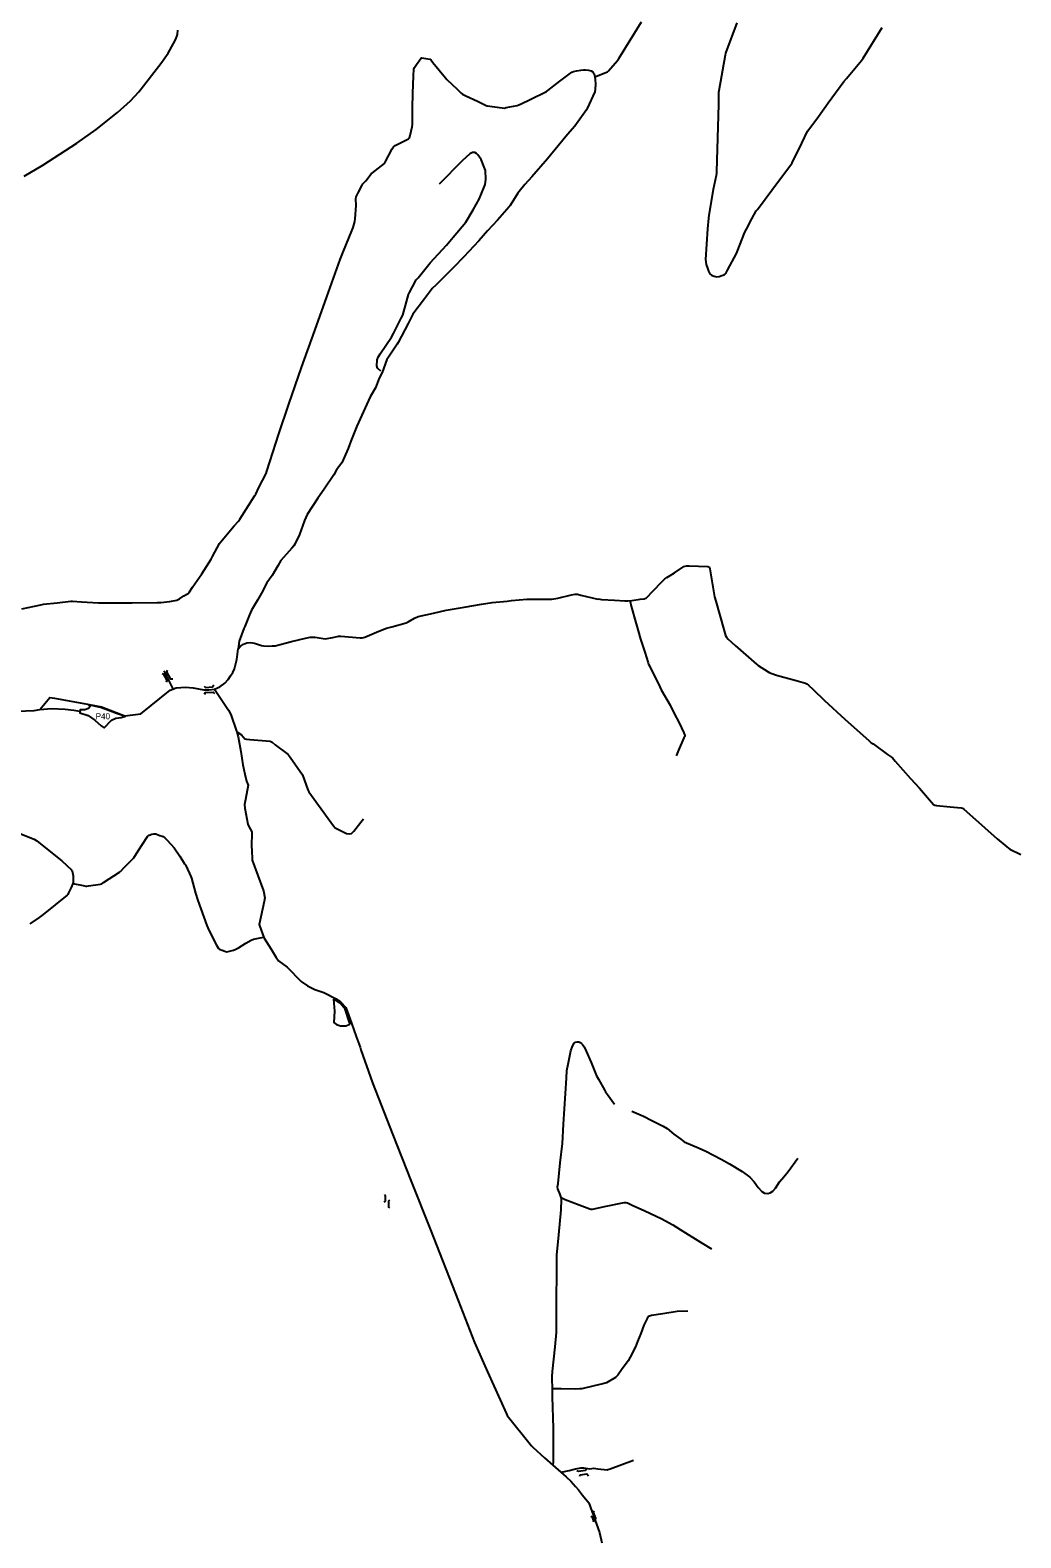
# Model space of a CAD drawing. Extents: x -439169 to -431590, y -1130011 to -1121081.
# Drawn here: x -436040 to -434407, y -1125656 to -1123172 of the extents above; entities that cross this region are included whole.
import ezdxf

# ---------------------------------------------------------------- set-up
doc = ezdxf.new("R2010")
doc.units = 0
for name, color, linetype in [('11811012_místní  komunikace_Stav', 7, 'Continuous'), ('11900012_účelová komunikace_Stav', 7, 'Continuous'), ('11930011_silniční most _ estakáda_Stav', 7, 'Continuous'), ('12080013_parkoviště mimo prostor komunikace_Stav', 7, 'Continuous')]:
    doc.layers.add(name, color=color, linetype=linetype)

msp = doc.modelspace()

# ---------------------------------------------------------------- linework, layer by layer
at = {"layer": '11811012_místní  komunikace_Stav'}
for points in [[(-436049.6, -1123412.6), (-436018.7, -1123394.7), (-435962.8, -1123358.3), (-435930.5, -1123335.7), (-435895.5, -1123307.6), (-435874.4, -1123288.7), (-435860.3, -1123273.9), (-435824.1, -1123227.2), (-435812.2, -1123209.9), (-435803.3, -1123194.1), (-435799.4, -1123186.7), (-435796.9, -1123179.4), (-435796.2, -1123172.1)], [(-435669.9, -1124181.7), (-435668.3, -1124182.3), (-435658.6, -1124185.6), (-435654.8, -1124186.5), (-435646, -1124186.8), (-435640.9, -1124186.6), (-435635.8, -1124186.2), (-435609.1, -1124179.2), (-435586.1, -1124173.7), (-435577.9, -1124172.1), (-435574.9, -1124172.1), (-435569.8, -1124172.3), (-435556.8, -1124174.4), (-435553.7, -1124174.6), (-435540.9, -1124172.5), (-435531.3, -1124170.5), (-435527.7, -1124170.4), (-435495.7, -1124173), (-435492.5, -1124173), (-435488.1, -1124171.9), (-435464.8, -1124162.2), (-435452.3, -1124157.2), (-435443.7, -1124155.2), (-435420.2, -1124148.4), (-435416.6, -1124146.8), (-435406.5, -1124140.8), (-435400.1, -1124137.8), (-435374.8, -1124132.3), (-435353.9, -1124127.6), (-435324.6, -1124122.6), (-435295.9, -1124117.7), (-435278.2, -1124115.2), (-435253.8, -1124112.9), (-435246.3, -1124111.9), (-435221, -1124109.4), (-435202.3, -1124109.5), (-435180.1, -1124109.4), (-435176.8, -1124109.1), (-435170, -1124107.6), (-435147.8, -1124102.5), (-435141.4, -1124101.2), (-435137.9, -1124101.4), (-435132, -1124103.1), (-435103.9, -1124109.5)], [(-435699.2, -1124208.8), (-435696.7, -1124191.4), (-435693.2, -1124186.8), (-435687.8, -1124183.6), (-435682.3, -1124181.2), (-435676.2, -1124180.9), (-435670, -1124181.8)], [(-436074, -1124294.5), (-436033, -1124292.8), (-436023.7, -1124291.1), (-436007.1, -1124271.2), (-435999.6, -1124272.3), (-435944.8, -1124282.4), (-435921.9, -1124287), (-435883.8, -1124301.4), (-435857.3, -1124298.1), (-435808.9, -1124259.2), (-435799.1, -1124255.4), (-435783.7, -1124254.6), (-435770.8, -1124255.4), (-435753.3, -1124259), (-435745.1, -1124259), (-435735.9, -1124257.5), (-435727.2, -1124253.9), (-435718.6, -1124247.6), (-435713.1, -1124241.7), (-435709.2, -1124235.8), (-435705.7, -1124230), (-435703.1, -1124224.3), (-435701.3, -1124217.7), (-435699.2, -1124208.8)], [(-435735.9, -1124257.5), (-435712.5, -1124292.4), (-435708.7, -1124299.6), (-435699.8, -1124326.7), (-435699.2, -1124328.2), (-435696.6, -1124336.1), (-435692.5, -1124360.5), (-435688.9, -1124382.2), (-435685.8, -1124397.5), (-435683, -1124409.4), (-435680.5, -1124415.7), (-435684.6, -1124439.6), (-435686.1, -1124447.6), (-435685.7, -1124453.7), (-435680.8, -1124480.1), (-435679.9, -1124482.7), (-435674.5, -1124492.6), (-435674.7, -1124517.9), (-435674.1, -1124522), (-435673.6, -1124539.5), (-435654.8, -1124589.9), (-435652.7, -1124601.3), (-435653.7, -1124607.6), (-435662.2, -1124645.6), (-435655.9, -1124662.6), (-435653.7, -1124667.9), (-435642.6, -1124686.2), (-435634.4, -1124699.6), (-435630.3, -1124705), (-435615.9, -1124715.8), (-435593, -1124739.2), (-435582.3, -1124746.6), (-435570.5, -1124752.3), (-435555.4, -1124757.5), (-435535.4, -1124767.8), (-435528, -1124772.6), (-435519.5, -1124782), (-435510.2, -1124807.8)], [(-436023.7, -1124291.1), (-436004.5, -1124289.5), (-435981.7, -1124290.7), (-435967.5, -1124292.2), (-435957.6, -1124294.1)]]:
    msp.add_lwpolyline(points, dxfattribs=at)
for points in [[(-435942.7, -1124283.3), (-435940.8, -1124286.3), (-435943.6, -1124289.8), (-435949.5, -1124291.7), (-435957.3, -1124291.6), (-435957.9, -1124296.6), (-435944.1, -1124301.3), (-435932.9, -1124309), (-435922.3, -1124318.1), (-435917.6, -1124321.6), (-435905.6, -1124308.7), (-435898.4, -1124305.3), (-435889.6, -1124304.2), (-435882.2, -1124302.4), (-435885.7, -1124301.7), (-435897.4, -1124297.8), (-435916.1, -1124290.8), (-435923.6, -1124287.9), (-435931.1, -1124286.1)], [(-435539.8, -1124768.2), (-435538.1, -1124788.1), (-435539.3, -1124807), (-435534.7, -1124810.1), (-435528.3, -1124812.1), (-435519.6, -1124812.1), (-435514.1, -1124810.1), (-435512.6, -1124808.6), (-435520.5, -1124784.7), (-435528.7, -1124775), (-435536.5, -1124770)]]:
    msp.add_lwpolyline(points, close=True, dxfattribs=at)
at = {"layer": '11900012_účelová komunikace_Stav'}
msp.add_line((-435803.7, -1124257.2), (-435818.6, -1124227.4), dxfattribs=at)
for points in [[(-435109.1, -1123249.1), (-435088.3, -1123240.8), (-435086.5, -1123239.1), (-435071.5, -1123221.8), (-435069.3, -1123218.8), (-435032, -1123158.1)], [(-434874.9, -1123159.9), (-434893.7, -1123210.1), (-434894.2, -1123213), (-434904.5, -1123272.1), (-434905.1, -1123275), (-434905.4, -1123294.6), (-434908.6, -1123405.1), (-434908.6, -1123407.6), (-434909.3, -1123411.3), (-434914.1, -1123434.6), (-434921.5, -1123476.7), (-434922, -1123481.7), (-434923.7, -1123499.2), (-434926.6, -1123549.8), (-434925.5, -1123557.9), (-434923.5, -1123564.2), (-434922, -1123569.3), (-434919.8, -1123573.4), (-434916.8, -1123575.8), (-434912.6, -1123577.3), (-434908, -1123578.4), (-434904.1, -1123577.8), (-434899.9, -1123576.4), (-434896.2, -1123575.1), (-434893.3, -1123572.7), (-434890.5, -1123567.3), (-434875.6, -1123540), (-434874.3, -1123537.1), (-434862.1, -1123505), (-434859.4, -1123499.9), (-434850.2, -1123482.9), (-434843.2, -1123469.5), (-434841.3, -1123467.3), (-434805, -1123418.6), (-434786.3, -1123393.8), (-434784.1, -1123390.7), (-434768.2, -1123358.2), (-434758.5, -1123338.5), (-434756.4, -1123335.9), (-434740.8, -1123314.5), (-434724.4, -1123291.8), (-434698.6, -1123256.8), (-434694.2, -1123251.6), (-434669.5, -1123222.1), (-434667.1, -1123218.3), (-434635.5, -1123167.8)], [(-435650.9, -1123902.2), (-435649.8, -1123898.5), (-435629.6, -1123837), (-435613.2, -1123788.3), (-435592.3, -1123728), (-435570.6, -1123666.7), (-435550.5, -1123611.2), (-435528.5, -1123550), (-435524.3, -1123539.1), (-435508.4, -1123500.1), (-435507.5, -1123497.2), (-435504.7, -1123487.1), (-435503.8, -1123482.7), (-435502.4, -1123461), (-435503.1, -1123449.9), (-435502.4, -1123446.5), (-435500.9, -1123443.2), (-435498.6, -1123438.9), (-435492.6, -1123427.3), (-435491.3, -1123425.3), (-435486.6, -1123420), (-435477.4, -1123408.8), (-435475.6, -1123407.1), (-435455.8, -1123391.5), (-435454.5, -1123389.4), (-435442.9, -1123367.6), (-435440.8, -1123364.2), (-435438.3, -1123362), (-435416.3, -1123351.3), (-435414.5, -1123349.7), (-435413.6, -1123345.5), (-435410, -1123331.4), (-435409.8, -1123327.6), (-435409.7, -1123300), (-435409.2, -1123276.6), (-435407.7, -1123247.2), (-435407.1, -1123236.3), (-435406.1, -1123233.6), (-435403.1, -1123228.7), (-435396, -1123218.7), (-435394.3, -1123217.4), (-435391.1, -1123218), (-435381.1, -1123220), (-435378.7, -1123221.3), (-435375.9, -1123225.3), (-435355.4, -1123250.8), (-435352.8, -1123253.4), (-435336, -1123269.5), (-435329.2, -1123275.9), (-435327, -1123277.5), (-435321.8, -1123280.4), (-435302.6, -1123289.1), (-435288.3, -1123296), (-435286.5, -1123296.7), (-435281.9, -1123297.3), (-435257.8, -1123300.4), (-435255.4, -1123299.7), (-435237.3, -1123295.9), (-435234.4, -1123295.2), (-435230.3, -1123293.3), (-435215.7, -1123286.3), (-435188.7, -1123273.1), (-435186.5, -1123271.4), (-435166.6, -1123256.2), (-435146.8, -1123241.5), (-435144.4, -1123240.4), (-435139.3, -1123239.2), (-435131.9, -1123237.8), (-435127.8, -1123237.3), (-435124.5, -1123237.3), (-435119.8, -1123237.8), (-435115.3, -1123239.3), (-435112.6, -1123240.5), (-435110.4, -1123244.2), (-435109.1, -1123249.1), (-435108.3, -1123253.8), (-435108.2, -1123260.2), (-435108.3, -1123269.9), (-435109.3, -1123273.7), (-435121.5, -1123300.9), (-435122.8, -1123303.3), (-435142.3, -1123330), (-435154, -1123343.8), (-435169.5, -1123362.5), (-435187.1, -1123383.9), (-435213.1, -1123413.5), (-435224.2, -1123426.5), (-435233.9, -1123437.6), (-435236, -1123440.8), (-435248.5, -1123460.9), (-435250.4, -1123463), (-435269.7, -1123484.8), (-435285.8, -1123502.6), (-435300.2, -1123518.9), (-435324.7, -1123545.3), (-435341.7, -1123563.3), (-435370.5, -1123591.4), (-435377.1, -1123597.9), (-435378.3, -1123599.2), (-435389.7, -1123614.7), (-435409, -1123640.1)], [(-435461.6, -1123734.1), (-435467, -1123728.7), (-435468.1, -1123725), (-435467.5, -1123715.1), (-435466.2, -1123710.6), (-435462.9, -1123705.1), (-435443.9, -1123678), (-435440.8, -1123671.7), (-435428.1, -1123646.4), (-435425.7, -1123641.6), (-435419.6, -1123619.6), (-435415.9, -1123607.7), (-435414.5, -1123604), (-435409.3, -1123594.9), (-435403.3, -1123583.6), (-435400, -1123580.1), (-435380.2, -1123555.4), (-435353.7, -1123526.5), (-435342.3, -1123513), (-435321.7, -1123488.4), (-435309.7, -1123467.9), (-435299.6, -1123450.4), (-435296.8, -1123444.1), (-435289.8, -1123426.3), (-435289.1, -1123422.4), (-435288.5, -1123417.6), (-435289.3, -1123403.1), (-435291.5, -1123398), (-435296.5, -1123385.3), (-435301.8, -1123377.7), (-435304.2, -1123375.1), (-435306.8, -1123373.6), (-435310.5, -1123373.8), (-435315.2, -1123375.8), (-435327.6, -1123387.1), (-435365.6, -1123425.9)], [(-435409, -1123640.1), (-435410.3, -1123642.2), (-435416.9, -1123655.3), (-435433.1, -1123686.7), (-435434.8, -1123689.1), (-435450.3, -1123712.2), (-435451.7, -1123714.4), (-435459.6, -1123736.3), (-435464.4, -1123745.3), (-435470.7, -1123761.3), (-435479.4, -1123775.9), (-435501.3, -1123824.3), (-435511.4, -1123849.4), (-435515.4, -1123861.1), (-435526.1, -1123885.1), (-435534.6, -1123896.3), (-435539.4, -1123904.5), (-435555.3, -1123928.5), (-435565.3, -1123943), (-435583.2, -1123970.1), (-435587.4, -1123980.1), (-435595.8, -1124002.8), (-435603.4, -1124019), (-435605, -1124021.7), (-435608.3, -1124025.4), (-435626.5, -1124045.9), (-435631.6, -1124054.6), (-435641, -1124070.2), (-435649.6, -1124082.5), (-435658.2, -1124099.7), (-435665, -1124110.9), (-435674.9, -1124127.5), (-435677.9, -1124135.2), (-435685.7, -1124154.6), (-435687.3, -1124157.8), (-435695.4, -1124178.9), (-435696.7, -1124191.4)], [(-436053.2, -1124125.4), (-436021.8, -1124118.7), (-436017.8, -1124117.9), (-435995.2, -1124115.3), (-435972.6, -1124112.7), (-435969.8, -1124112.9), (-435954.7, -1124113.7), (-435926.9, -1124115.7), (-435914.2, -1124115.6), (-435871.6, -1124115.5), (-435830.3, -1124115.1), (-435824.2, -1124114.7), (-435809.9, -1124113.1), (-435800.5, -1124111.9), (-435797.8, -1124111.2), (-435793.7, -1124109.1), (-435786.1, -1124103.9), (-435779.4, -1124099.9), (-435777.1, -1124097.6), (-435771.8, -1124089.8), (-435756.6, -1124067.6), (-435741.4, -1124043.5), (-435739.2, -1124039.1), (-435727.6, -1124017.6), (-435725.8, -1124015.5), (-435703.2, -1123988.9), (-435696.5, -1123980.9), (-435694.2, -1123977.6), (-435669.2, -1123938.8), (-435667.6, -1123936.3), (-435662.6, -1123925.5), (-435650.9, -1123902.2)], [(-434990.3, -1124073.6), (-434985, -1124070.4), (-434977.8, -1124065.8), (-434962.3, -1124055.8), (-434958.3, -1124054.3), (-434953.8, -1124054.3), (-434923.1, -1124055.8), (-434920.4, -1124056.7), (-434919.6, -1124059.4), (-434918.2, -1124069.2), (-434911.7, -1124105.6), (-434909.6, -1124112.7), (-434896.4, -1124159.2), (-434893.6, -1124169.2), (-434892.3, -1124172), (-434889.2, -1124175.2), (-434877.6, -1124185.6), (-434842.5, -1124216.7), (-434839.7, -1124218.9), (-434823.4, -1124229.3), (-434820.8, -1124230.7), (-434817.2, -1124231.9), (-434809.5, -1124234.9), (-434777.5, -1124243.6), (-434762.1, -1124248), (-434760, -1124249), (-434757, -1124251.2), (-434749.4, -1124258.3), (-434730.4, -1124276.5), (-434697.4, -1124307.1), (-434657.2, -1124342.7), (-434653.6, -1124345.9), (-434650.6, -1124348), (-434627.1, -1124365.3), (-434618.6, -1124371.1), (-434616.6, -1124373.5), (-434614.1, -1124376.1), (-434588.9, -1124404.7), (-434574.1, -1124421), (-434550.9, -1124447.6), (-434548.8, -1124449), (-434546.2, -1124449.3), (-434523.8, -1124451.4), (-434505.5, -1124453.4), (-434503.2, -1124453.8), (-434501, -1124455.5), (-434486.7, -1124468.3), (-434445.9, -1124504.1), (-434430.2, -1124517.5), (-434427.6, -1124519.7), (-434425, -1124521.1), (-434407.1, -1124529.9)], [(-435103.6, -1124109.1), (-435098.1, -1124110.1), (-435076.5, -1124111.2), (-435059.9, -1124112), (-435054.7, -1124112.4), (-435047.9, -1124111.7), (-435034.5, -1124109.5), (-435027.6, -1124109), (-435025.3, -1124108), (-435024.7, -1124107.6), (-434999.9, -1124082.2), (-434993.5, -1124076), (-434990.3, -1124073.6)], [(-435050.8, -1124113.5), (-435049.1, -1124120.8), (-435042.2, -1124146), (-435037.5, -1124161.8), (-435034.1, -1124175.2), (-435026.9, -1124197), (-435021.3, -1124214.5), (-435020.5, -1124216.3), (-435019.1, -1124219.5), (-435002, -1124254.1), (-434999.6, -1124259), (-434985.2, -1124284.2), (-434978.1, -1124297.6), (-434969.9, -1124313.4), (-434962.7, -1124329.5), (-434961, -1124334), (-434960.8, -1124335.7), (-434962.2, -1124337.9), (-434971.5, -1124358.2), (-434974.5, -1124366.5), (-434974.9, -1124367.6)], [(-435699.2, -1124328.2), (-435691.1, -1124333.2), (-435685.7, -1124339.5), (-435683, -1124340.2), (-435677.8, -1124340.6), (-435644.2, -1124343.5), (-435640.6, -1124344.8), (-435635.6, -1124349.2), (-435614.2, -1124365.6), (-435611.3, -1124369.7), (-435590.6, -1124399), (-435582, -1124423.8), (-435580.3, -1124426.8), (-435560.3, -1124454.6), (-435548.3, -1124471), (-435539.8, -1124482.6), (-435537.1, -1124485.9), (-435530.2, -1124489.6), (-435518.3, -1124495.3), (-435513.8, -1124496), (-435509.8, -1124495.5), (-435506.2, -1124491.8), (-435494.5, -1124477), (-435490.1, -1124471.1)], [(-436064.6, -1124492.1), (-436033.1, -1124505), (-436028.3, -1124507.6), (-436022.6, -1124512.5), (-435987.6, -1124540.4), (-435971.6, -1124555.5), (-435970.2, -1124557.1), (-435968.9, -1124565.2), (-435968.7, -1124572.4), (-435968.7, -1124576.1), (-435969.4, -1124577.9), (-435972.2, -1124584.2), (-435976.2, -1124593.2), (-435977.3, -1124595.8), (-435978.6, -1124596.9), (-436018.2, -1124629.1), (-436024.5, -1124633.7), (-436038.3, -1124643.3), (-436040.1, -1124644.9)], [(-435969.4, -1124577.9), (-435952, -1124581.3), (-435947.9, -1124582), (-435946.2, -1124582), (-435943.4, -1124581.8), (-435923.9, -1124579), (-435921.3, -1124578.2), (-435918.7, -1124576.3), (-435892.5, -1124559.4), (-435890.5, -1124557.9), (-435885, -1124552.1), (-435870.8, -1124537.6), (-435868.9, -1124535.5), (-435861.7, -1124523.9), (-435846.2, -1124500.2), (-435843.7, -1124498.2), (-435838.9, -1124496.5), (-435835.9, -1124495.9), (-435832.6, -1124496.2), (-435827.3, -1124498), (-435820.5, -1124500.4), (-435817.7, -1124502.6), (-435813.7, -1124506.6), (-435802.5, -1124519.2), (-435793.1, -1124533.1), (-435785, -1124545.3), (-435783.4, -1124547.2), (-435776.9, -1124561.6), (-435774.6, -1124566.1), (-435773.7, -1124569.2), (-435767.1, -1124593.6), (-435763, -1124605.8), (-435748.4, -1124647.1), (-435746.8, -1124651), (-435739.4, -1124666), (-435732.6, -1124679.3), (-435729, -1124684.8), (-435727, -1124686.6), (-435723.4, -1124687.6), (-435718.8, -1124689.5), (-435716.1, -1124690.2), (-435713.5, -1124690.1), (-435704.6, -1124687.5), (-435700.5, -1124685.9), (-435696.1, -1124683.8), (-435684.1, -1124676.4), (-435675.2, -1124671.2), (-435671.3, -1124669.6), (-435660.4, -1124667.3), (-435654.7, -1124666.1)], [(-435510.2, -1124807.8), (-435502.1, -1124829.7), (-435495.8, -1124847.4), (-435494.5, -1124851.7), (-435475.4, -1124906.5), (-435442.1, -1124991.9), (-435412.4, -1125067.1), (-435380, -1125148.4), (-435334.5, -1125265), (-435307.5, -1125333.8), (-435285.9, -1125382.5), (-435254.8, -1125451.7), (-435253.5, -1125454.5), (-435213.4, -1125504.3), (-435211.5, -1125506.3), (-435192.1, -1125523.9), (-435178.3, -1125536.1), (-435156.1, -1125555.3), (-435148.7, -1125562.6), (-435140.8, -1125571.5), (-435136.2, -1125576.7), (-435129.2, -1125585.5), (-435119, -1125598.3), (-435101.6, -1125646.9), (-435097.4, -1125664)], [(-435178.3, -1125536.1), (-435177.2, -1125532), (-435177.2, -1125505.5), (-435177.3, -1125475.1), (-435178.6, -1125423.3), (-435179, -1125410.2), (-435179.5, -1125393), (-435179.5, -1125390.1), (-435178.6, -1125381.9), (-435174.4, -1125341), (-435172, -1125317.8), (-435172, -1125315.8), (-435172.1, -1125271.7), (-435171.7, -1125211.1), (-435171.5, -1125190.1), (-435168.6, -1125156.9), (-435164.8, -1125115.6), (-435163.8, -1125098.6), (-435164.3, -1125095), (-435166.3, -1125090.3), (-435169.9, -1125081.1), (-435170.4, -1125077.7), (-435169.6, -1125072), (-435166, -1125038.2), (-435162.4, -1125006.4), (-435160.5, -1124974.1), (-435155.9, -1124898.7), (-435155, -1124886.1), (-435153.3, -1124875.6), (-435148.5, -1124853.8), (-435145.9, -1124845.8), (-435143.2, -1124840.9), (-435141.2, -1124839.2), (-435138, -1124838.8), (-435135.4, -1124838.8), (-435133, -1124839.6), (-435130.8, -1124841.2), (-435129.3, -1124842.9), (-435126.8, -1124847), (-435123.3, -1124854), (-435114.9, -1124872.9), (-435106.1, -1124894.6), (-435103.2, -1124900.1), (-435092.8, -1124919.1), (-435091.6, -1124920.9), (-435088.3, -1124925.6), (-435076.6, -1124941.5)], [(-435048.2, -1124953), (-435029, -1124960.9), (-435014.9, -1124968.2), (-434996.7, -1124977.4), (-434990.1, -1124981.4), (-434978.7, -1124990.8), (-434967.2, -1124999.2), (-434962, -1125003.2), (-434937.2, -1125013.8), (-434926.3, -1125018.9), (-434901, -1125031.9), (-434887.4, -1125039.7), (-434866.3, -1125052.1), (-434853.8, -1125061.9), (-434846.7, -1125069.2), (-434840.1, -1125078.7), (-434833.7, -1125085.3), (-434829.7, -1125087.9), (-434824.2, -1125088.4), (-434820.2, -1125087.2), (-434815.9, -1125084.6), (-434811.2, -1125079.6), (-434805, -1125069.4), (-434797.5, -1125061.1), (-434790.4, -1125052.6), (-434774.5, -1125030.6)], [(-435164.3, -1125095), (-435157.8, -1125098.7), (-435134.9, -1125107.3), (-435117.5, -1125113.6), (-435115.8, -1125114.2), (-435113.2, -1125114.2), (-435090.3, -1125109.5), (-435060.6, -1125103.4), (-435058.2, -1125103.5), (-435055, -1125104), (-435047.7, -1125107.9), (-435026.9, -1125116.9), (-434999.9, -1125130), (-434980.7, -1125140.3), (-434968.7, -1125147.8), (-434935.2, -1125168.5), (-434917, -1125179.9)], [(-434955.6, -1125282.3), (-434973.5, -1125282.8), (-434996.8, -1125286.8), (-435015.6, -1125289.6), (-435020.7, -1125291), (-435022.8, -1125294.4), (-435028.5, -1125305.4), (-435033.1, -1125319), (-435039, -1125332.5), (-435042.3, -1125341.2), (-435050.8, -1125358.3), (-435054.3, -1125364), (-435064.9, -1125379.1), (-435071.2, -1125387.9), (-435073, -1125389.7), (-435075, -1125391.6), (-435089.9, -1125400.6), (-435092, -1125401.1), (-435095.8, -1125402.4), (-435110, -1125405.6), (-435130.3, -1125410.3), (-435133.9, -1125410.6), (-435140.2, -1125410.7), (-435164.3, -1125410.2), (-435179, -1125410.2)], [(-435164.4, -1125547.8), (-435151.4, -1125545), (-435140.7, -1125542.3), (-435132.1, -1125540.4), (-435127.1, -1125540.7), (-435117.6, -1125542.1), (-435110.5, -1125541.2), (-435104, -1125542), (-435089, -1125544), (-435087.4, -1125543.4), (-435083.9, -1125542.4), (-435045.3, -1125527.7)]]:
    msp.add_lwpolyline(points, dxfattribs=at)
at = {"layer": '11930011_silniční most _ estakáda_Stav'}
for points in [[(-435804.6, -1124241), (-435807.9, -1124241), (-435814.2, -1124229.1), (-435813, -1124226.6)], [(-435822.2, -1124232.1), (-435820.1, -1124232.4), (-435814.5, -1124243.6), (-435815.4, -1124246.1)], [(-435752.9, -1124252.5), (-435750.8, -1124255), (-435738.9, -1124253.9), (-435736.7, -1124250.6)], [(-435752.5, -1124266.1), (-435750.4, -1124263.4), (-435738.1, -1124262.7), (-435735.9, -1124265)], [(-435455.7, -1125090.3), (-435454.5, -1125092.2), (-435454.8, -1125101.4), (-435456.6, -1125103)], [(-435447.5, -1125099.5), (-435449.1, -1125101.1), (-435449.2, -1125110.9), (-435447.5, -1125112)], [(-435139, -1125544.8), (-435136, -1125545.9), (-435124.3, -1125544.5), (-435123, -1125541.9)], [(-435134, -1125554.2), (-435133.3, -1125551.8), (-435122, -1125550.6), (-435119.7, -1125553.5)], [(-435115.9, -1125620.3), (-435113.9, -1125620.5), (-435111.3, -1125628), (-435111.7, -1125630)], [(-435111, -1125611.5), (-435111.8, -1125613.4), (-435108.1, -1125623.2), (-435106.3, -1125623.6)]]:
    msp.add_lwpolyline(points, dxfattribs=at)

# ---------------------------------------------------------------- texts
at = {"layer": '12080013_parkoviště mimo prostor komunikace_Stav'}
msp.add_text('P40', height=10, dxfattribs=at).set_placement((-435931.7, -1124307.3))

doc.saveas('drawing.dxf')
